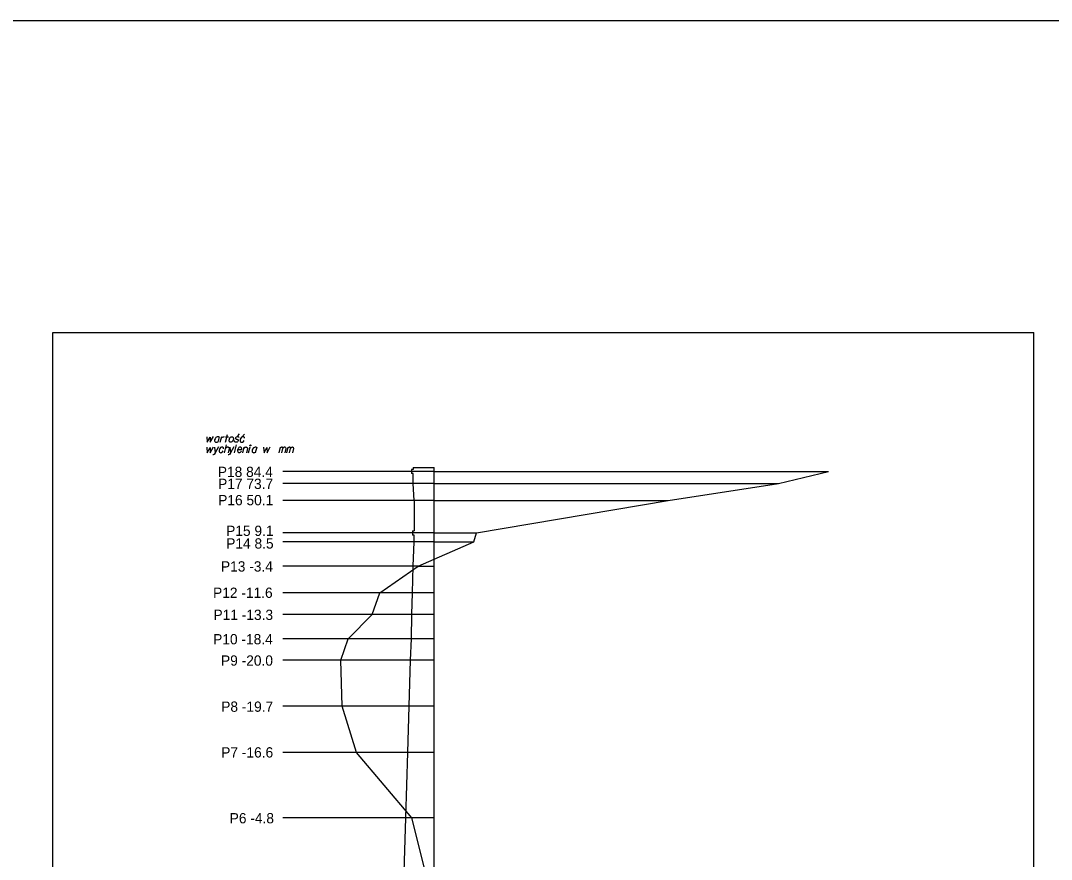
# Model space of a CAD drawing. Extents: x 138 to 6653, y -177 to 1520.
# Drawn here: x 376.31 to 398.38, y 20.71 to 38.66 of the extents above; entities that cross this region are included whole.
import ezdxf

# ---------------------------------------------------------------- set-up
doc = ezdxf.new("R2010")
doc.units = 0
for name, color, linetype in [('15 listopad 2008', 7, 'Continuous'), ('Ramka do drukowania', 7, 'Continuous'), ('Standart wykresów', 7, 'Continuous'), ('Wykresy 4 maj 2008', 7, 'Continuous')]:
    doc.layers.add(name, color=color, linetype=linetype)

msp = doc.modelspace()

# ---------------------------------------------------------------- linework, layer by layer
at = {"layer": '15 listopad 2008'}
msp.add_lwpolyline([(287.418, 38.661), (413.872, 38.661), (413.872, -75.347), (287.418, -75.347)], close=True, dxfattribs=at)
msp.add_lwpolyline([(385.168, 13.297), (385.638, 14.742), (385.798, 16.118), (385.628, 17.485), (385.468, 18.843), (385.038, 20.202), (384.688, 21.593), (383.508, 22.995), (383.198, 23.989), (383.168, 24.969), (383.328, 25.428), (383.838, 25.945), (384.008, 26.413), (384.828, 26.981), (386.018, 27.507), (386.078, 27.694), (390.178, 28.392), (392.538, 28.755), (393.608, 29.011)], dxfattribs=at)
at = {"layer": 'Ramka do drukowania'}
for p, q in [((377.007, 2.285), (377.007, 31.985)), ((377.007, 31.985), (398.007, 31.985)), ((398.007, 2.285), (398.007, 31.985))]:
    msp.add_line(p, q, dxfattribs=at)
at = {"layer": 'Standart wykresów'}
for p, q in [((385.168, 29.011), (381.931, 29.011)), ((384.685, 29.053), (384.685, 29.011)), ((384.722, 29.053), (384.685, 29.053)), ((384.685, 29.011), (384.685, 28.969)), ((384.722, 28.969), (384.685, 28.969)), ((384.722, 29.095), (384.722, 29.053)), ((384.722, 29.095), (385.168, 29.095)), ((384.722, 28.755), (384.722, 28.969)), ((385.168, 9.011), (385.168, 29.095)), ((385.168, 28.755), (381.931, 28.755)), ((384.737, 28.392), (384.722, 28.755)), ((385.168, 28.392), (381.931, 28.392)), ((384.737, 28.392), (384.737, 27.738)), ((385.168, 27.694), (381.931, 27.694)), ((384.707, 27.738), (384.707, 27.694)), ((384.707, 27.738), (384.737, 27.738)), ((384.707, 27.694), (384.707, 27.65)), ((384.741, 27.65), (384.707, 27.65)), ((384.737, 27.507), (384.741, 27.65)), ((385.168, 27.507), (381.931, 27.507)), ((384.722, 26.981), (384.737, 27.507)), ((384.828, 26.981), (381.931, 26.981)), ((384.707, 26.413), (384.722, 26.981)), ((384.828, 26.981), (385.168, 26.981)), ((384.008, 26.413), (381.931, 26.413)), ((384.692, 25.945), (384.707, 26.413)), ((383.838, 25.945), (381.931, 25.945)), ((384.68, 25.428), (384.692, 25.945)), ((383.328, 25.428), (381.931, 25.428)), ((384.662, 24.969), (384.68, 25.428)), ((383.168, 24.969), (381.931, 24.969)), ((384.635, 23.989), (384.662, 24.969)), ((383.198, 23.989), (381.931, 23.989)), ((384.605, 22.995), (384.635, 23.989)), ((383.508, 22.995), (381.931, 22.995)), ((384.565, 21.593), (384.605, 22.995)), ((384.688, 21.593), (381.931, 21.593)), ((384.521, 20.202), (384.565, 21.593))]:
    msp.add_line(p, q, dxfattribs=at)
for points in [[(380.704, 29.635), (380.747, 29.801)], [(380.992, 29.813), (380.959, 29.776)], [(381.108, 29.812), (381.075, 29.775)], [(380.301, 29.754), (380.311, 29.635), (380.374, 29.744), (380.375, 29.635), (380.445, 29.757)], [(380.565, 29.745), (380.556, 29.751), (380.534, 29.751), (380.521, 29.749), (380.497, 29.736), (380.477, 29.712), (380.468, 29.687), (380.467, 29.674), (380.468, 29.664), (380.472, 29.655), (380.48, 29.644), (380.489, 29.638), (380.504, 29.635), (380.514, 29.636), (380.525, 29.638), (380.539, 29.645)], [(380.568, 29.755), (380.536, 29.635)], [(380.59, 29.635), (380.623, 29.759)], [(380.615, 29.729), (380.621, 29.734), (380.636, 29.745), (380.652, 29.751), (380.663, 29.755), (380.682, 29.759)], [(380.683, 29.412), (380.726, 29.579)], [(380.704, 29.755), (380.767, 29.755)], [(380.836, 29.755), (380.845, 29.755), (380.856, 29.75), (380.866, 29.736), (380.867, 29.729), (380.869, 29.723), (380.869, 29.717), (380.869, 29.698), (380.865, 29.685), (380.858, 29.669), (380.85, 29.656), (380.837, 29.644), (380.825, 29.635), (380.806, 29.635), (380.798, 29.638), (380.79, 29.644), (380.786, 29.651), (380.781, 29.666), (380.781, 29.69), (380.784, 29.698), (380.789, 29.715), (380.794, 29.724), (380.797, 29.729), (380.81, 29.744), (380.823, 29.751), (380.836, 29.755)], [(380.992, 29.736), (380.988, 29.745), (380.979, 29.751), (380.971, 29.754), (380.959, 29.755), (380.948, 29.754), (380.933, 29.746), (380.922, 29.736), (380.918, 29.727), (380.917, 29.716), (380.92, 29.71), (380.925, 29.706), (380.928, 29.704), (380.935, 29.702), (380.945, 29.7), (380.958, 29.698), (380.966, 29.695), (380.972, 29.687), (380.975, 29.678), (380.973, 29.666), (380.968, 29.656), (380.958, 29.644), (380.948, 29.639), (380.938, 29.636), (380.925, 29.635), (380.909, 29.636), (380.899, 29.642), (380.894, 29.648), (380.891, 29.657), (380.891, 29.666), (380.895, 29.674)], [(380.895, 29.412), (380.938, 29.579)], [(381.107, 29.72), (381.105, 29.736), (381.099, 29.746), (381.091, 29.751), (381.075, 29.754), (381.061, 29.754), (381.043, 29.742), (381.028, 29.723), (381.018, 29.703), (381.014, 29.689), (381.014, 29.666), (381.015, 29.659), (381.02, 29.648), (381.032, 29.638), (381.045, 29.635), (381.06, 29.636), (381.068, 29.639), (381.085, 29.651), (381.098, 29.673)], [(381.233, 29.579), (381.239, 29.579), (381.243, 29.576), (381.247, 29.571), (381.247, 29.564), (381.243, 29.559), (381.239, 29.556), (381.233, 29.556), (381.229, 29.559), (381.225, 29.564), (381.225, 29.571), (381.229, 29.576), (381.233, 29.579)], [(380.3, 29.532), (380.31, 29.412), (380.373, 29.521), (380.374, 29.412), (380.444, 29.534)], [(380.55, 29.534), (380.483, 29.412), (380.462, 29.377), (380.457, 29.374), (380.45, 29.372), (380.437, 29.369), (380.432, 29.369)], [(380.466, 29.533), (380.483, 29.412)], [(380.661, 29.498), (380.659, 29.513), (380.653, 29.524), (380.645, 29.529), (380.629, 29.532), (380.615, 29.532), (380.597, 29.52), (380.582, 29.5), (380.572, 29.48), (380.568, 29.466), (380.568, 29.444), (380.569, 29.436), (380.574, 29.426), (380.586, 29.415), (380.599, 29.412), (380.614, 29.414), (380.622, 29.416), (380.639, 29.428), (380.652, 29.45)], [(380.708, 29.508), (380.712, 29.513), (380.717, 29.521), (380.721, 29.525), (380.724, 29.528), (380.728, 29.53), (380.731, 29.532), (380.735, 29.533), (380.739, 29.534), (380.748, 29.534), (380.755, 29.533), (380.763, 29.53), (380.768, 29.528), (380.772, 29.524), (380.776, 29.518), (380.779, 29.515), (380.78, 29.512), (380.782, 29.507), (380.782, 29.503), (380.758, 29.412)], [(380.877, 29.534), (380.81, 29.412), (380.789, 29.377), (380.784, 29.374), (380.777, 29.372), (380.764, 29.369), (380.759, 29.369)], [(380.793, 29.533), (380.81, 29.412)], [(380.964, 29.482), (381.048, 29.482), (381.049, 29.495), (381.047, 29.507), (381.042, 29.518), (381.026, 29.53), (381.013, 29.532), (381.002, 29.529), (380.988, 29.521), (380.979, 29.512), (380.971, 29.498), (380.966, 29.487), (380.96, 29.465), (380.96, 29.45), (380.962, 29.439), (380.966, 29.428), (380.981, 29.414), (380.992, 29.412), (381.002, 29.414), (381.004, 29.414), (381.021, 29.422), (381.03, 29.431), (381.034, 29.437), (381.035, 29.439), (381.042, 29.45)], [(381.072, 29.412), (381.104, 29.533)], [(381.097, 29.504), (381.1, 29.511), (381.106, 29.518), (381.11, 29.522), (381.115, 29.528), (381.12, 29.53), (381.127, 29.533), (381.133, 29.534), (381.138, 29.534), (381.145, 29.533), (381.15, 29.53), (381.155, 29.528), (381.161, 29.524), (381.166, 29.518), (381.168, 29.515), (381.171, 29.509), (381.174, 29.503), (381.15, 29.412)], [(381.196, 29.412), (381.23, 29.539)], [(381.367, 29.522), (381.358, 29.529), (381.336, 29.529), (381.323, 29.526), (381.299, 29.513), (381.28, 29.49), (381.271, 29.465), (381.269, 29.452), (381.271, 29.441), (381.274, 29.432), (381.282, 29.422), (381.291, 29.415), (381.306, 29.412), (381.316, 29.414), (381.327, 29.415), (381.341, 29.423)], [(381.37, 29.533), (381.339, 29.412)], [(381.515, 29.532), (381.526, 29.412), (381.588, 29.521), (381.59, 29.412), (381.659, 29.534)], [(381.848, 29.412), (381.878, 29.532)], [(381.87, 29.5), (381.876, 29.515), (381.883, 29.522), (381.891, 29.528), (381.899, 29.532), (381.904, 29.534), (381.912, 29.534), (381.914, 29.533), (381.919, 29.528), (381.925, 29.521), (381.929, 29.509), (381.93, 29.503), (381.936, 29.515), (381.944, 29.522), (381.952, 29.528), (381.96, 29.532), (381.967, 29.534), (381.973, 29.534), (381.978, 29.533), (381.982, 29.528), (381.986, 29.521), (381.99, 29.509), (381.991, 29.503), (381.969, 29.412)], [(381.908, 29.412), (381.93, 29.503)], [(382.014, 29.412), (382.044, 29.532)], [(382.036, 29.5), (382.042, 29.515), (382.049, 29.522), (382.057, 29.528), (382.065, 29.532), (382.07, 29.534), (382.078, 29.534), (382.08, 29.533), (382.086, 29.528), (382.091, 29.521), (382.095, 29.509), (382.096, 29.503), (382.103, 29.515), (382.111, 29.522), (382.118, 29.528), (382.126, 29.532), (382.133, 29.534), (382.139, 29.534), (382.145, 29.533), (382.148, 29.528), (382.152, 29.521), (382.156, 29.509), (382.158, 29.503), (382.135, 29.412)], [(382.074, 29.412), (382.096, 29.503)]]:
    msp.add_lwpolyline(points, dxfattribs=at)
at = {"layer": 'Wykresy 4 maj 2008'}
for p, q in [((385.168, 29.011), (393.608, 29.011)), ((385.168, 28.755), (392.538, 28.755)), ((385.168, 28.392), (390.178, 28.392)), ((385.168, 27.694), (386.078, 27.694)), ((385.168, 27.507), (386.018, 27.507)), ((385.168, 26.413), (384.008, 26.413)), ((385.168, 25.945), (383.838, 25.945)), ((385.168, 25.428), (383.328, 25.428)), ((385.168, 24.969), (383.168, 24.969)), ((385.168, 23.989), (383.198, 23.989)), ((385.168, 22.995), (383.508, 22.995)), ((385.168, 21.593), (384.688, 21.593))]:
    msp.add_line(p, q, dxfattribs=at)

# ---------------------------------------------------------------- texts
for s, p in [('P18 84.4', (380.537, 28.892)), ('P17 73.7', (380.543, 28.636)), ('P16 50.1', (380.545, 28.287)), ('P15 9.1', (380.715, 27.63)), ('P14 8.5', (380.717, 27.36)), ('P13 -3.4', (380.604, 26.868)), ('P12 -11.6', (380.435, 26.304)), ('P11 -13.3', (380.444, 25.832)), ('P10 -18.4', (380.437, 25.31)), ('P9 -20.0', (380.605, 24.853)), ('P8 -19.7', (380.61, 23.866)), ('P7 -16.6', (380.61, 22.887)), ('P6 -4.8', (380.791, 21.478))]:
    msp.add_text(s, height=0.22, dxfattribs=at).set_placement(p)

doc.saveas('drawing.dxf')
